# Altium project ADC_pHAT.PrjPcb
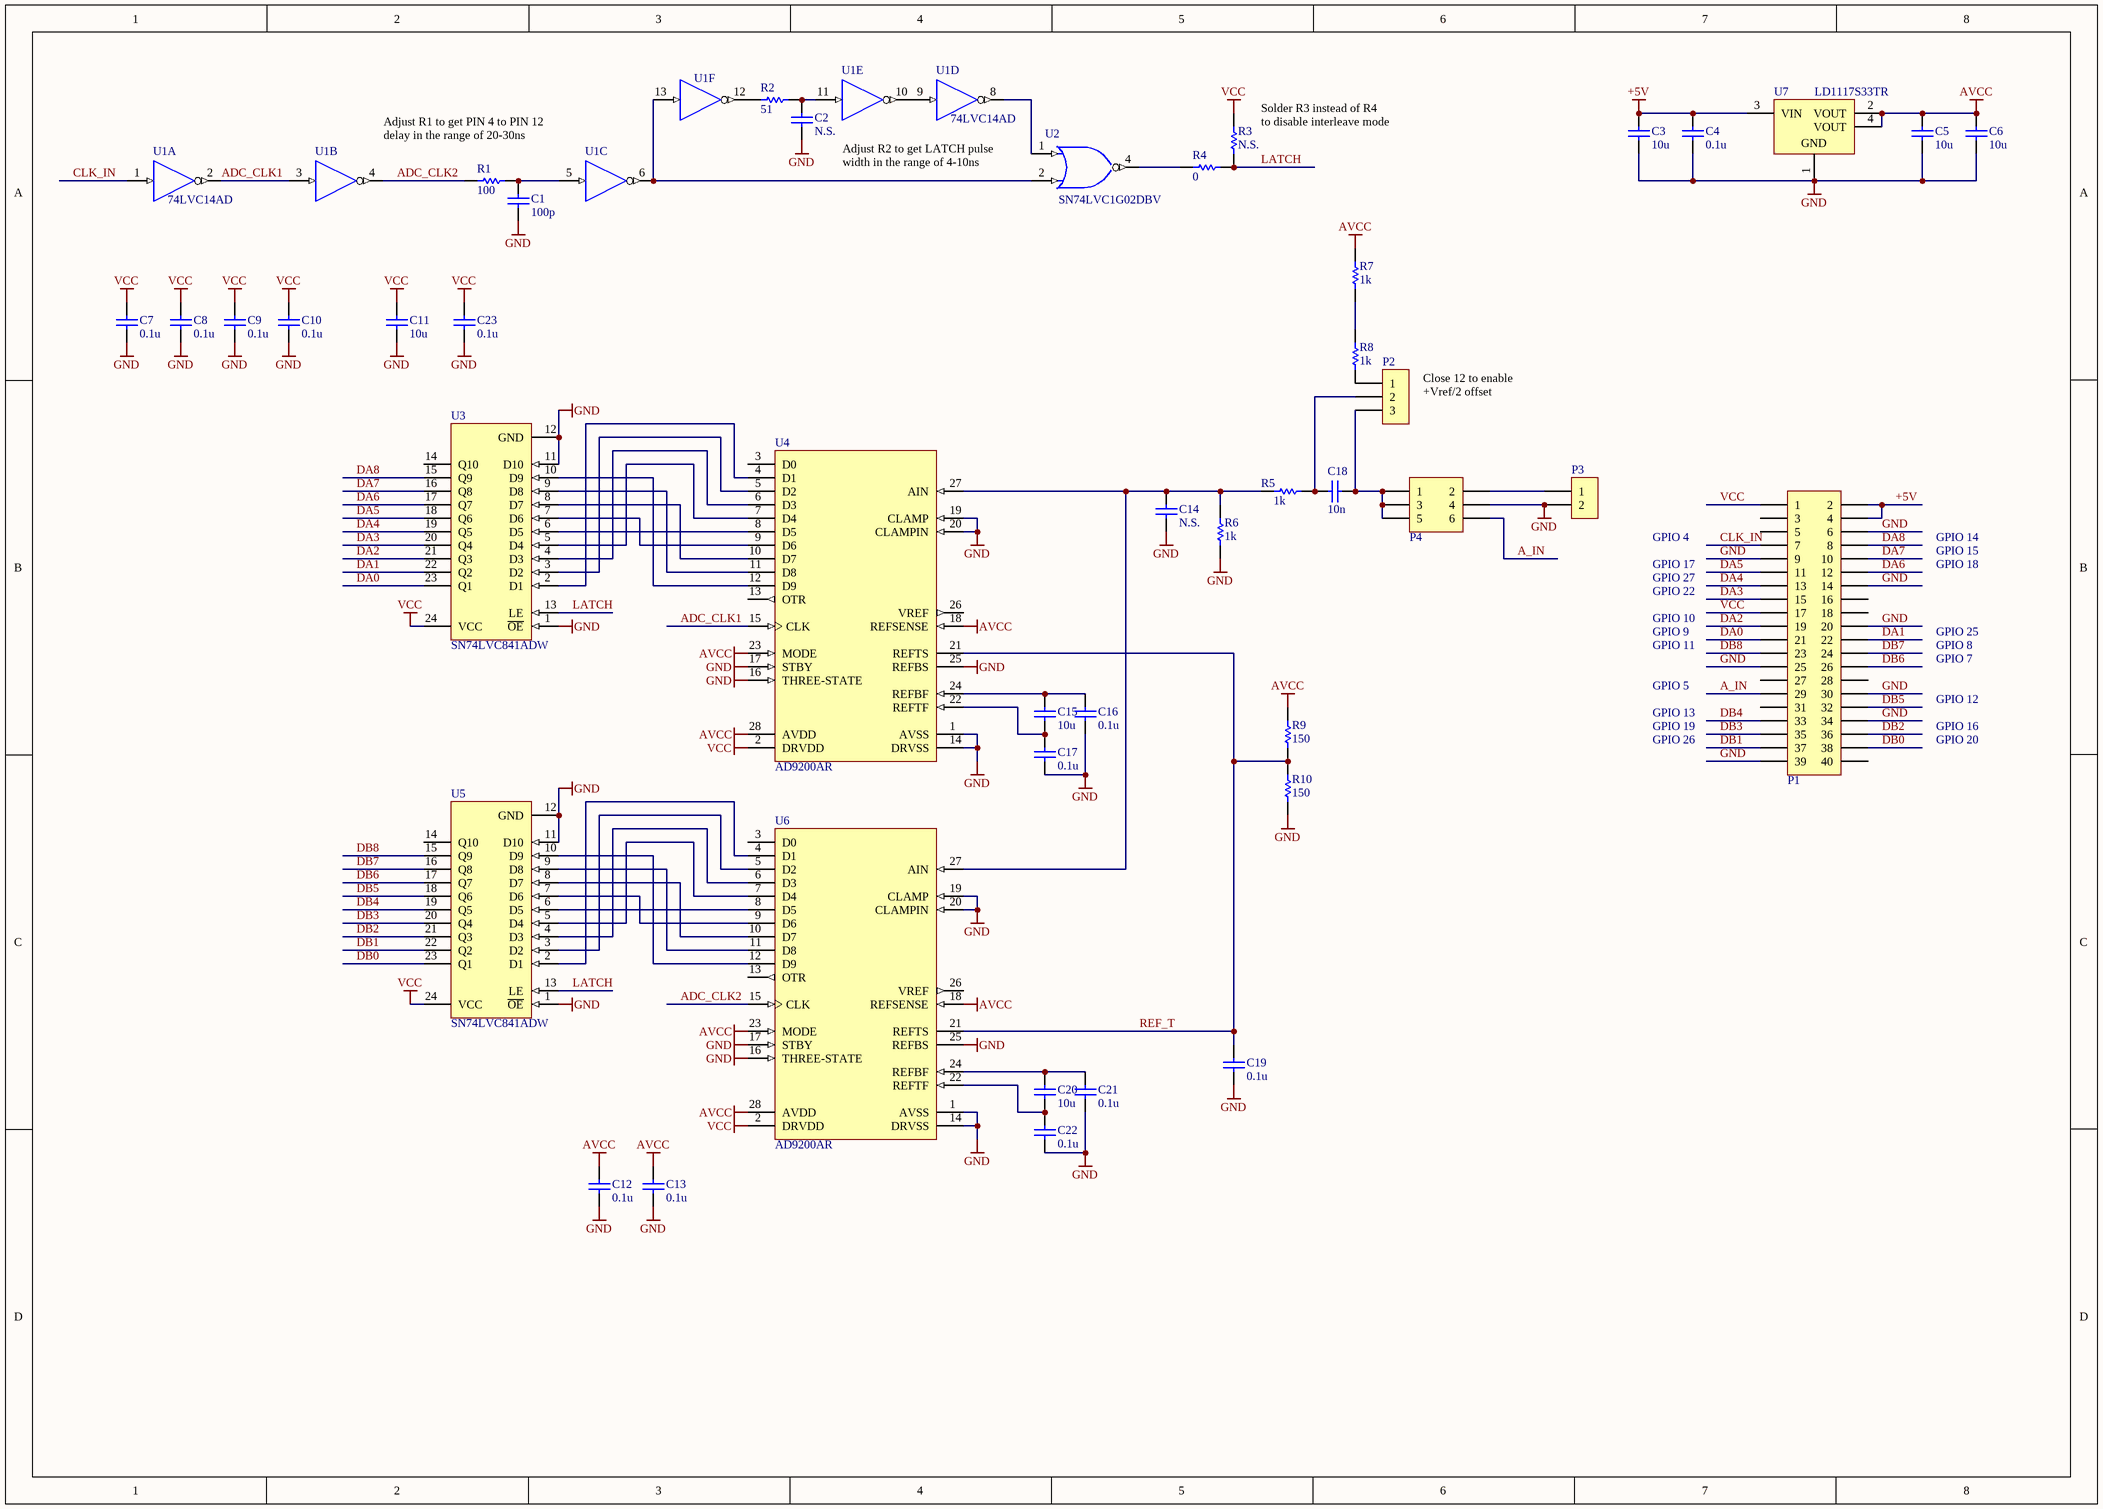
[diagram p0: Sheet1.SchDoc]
1 sheet, 44 parts. Net scope: global (net labels, ports and power ports of the same name join across sheets).
Board file: PCB1.PcbDoc

## Sheet Sheet1.SchDoc
size A3

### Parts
C1  100p  [0805RC]
C2  N.S.  [0805RC]
C3  10u  [1206RC]
C4  0.1u  [0805RC]
C5  10u  [1206RC]
C6  10u  [1206RC]
C7  0.1u  [0805RC]
C8  0.1u  [0805RC]
C9  0.1u  [0805RC]
C10  0.1u  [0805RC]
C11  10u  [1206RC]
C12  0.1u  [0805RC]
C13  0.1u  [0805RC]
C14  N.S.  [0805RC]
C15  10u  [1206RC]
C16  0.1u  [0805RC]
C17  0.1u  [0805RC]
C18  10n  [0805RC]
C19  0.1u  [0805RC]
C20  10u  [1206RC]
C21  0.1u  [0805RC]
C22  0.1u  [0805RC]
C23  0.1u  [0805RC]
P1  Header 20X2  [PLD-40]  (value not drawn)
P2  PLS-3  [PLS-3]  (value not drawn)
P3  Header 2  [SCSL-2]  (value not drawn)
P4  Header 3X2  [PBD-6]  (value not drawn)
R1  100  [0805R]
R2  51  [0805R]
R3  N.S.  [0805R]
R4  0  [0805R]
R5  1k  [0805R]
R6  1k  [0805R]
R7  1k  [0805R]
R8  1k  [0805R]
R9  150  [0805R]
R10  150  [0805R]
U1  74LVC14AD  [M14A_N]  (parts A,B,C,D,E,F of 6)
U2  SN74LVC1G02DBV  [SOT-23-5L]
U3  SN74LVC841ADW  [DW024_N]
U4  AD9200AR  [RS-28_N]
U5  SN74LVC841ADW  [DW024_N]
U6  AD9200AR  [RS-28_N]
U7  LD1117S33TR  [SOT223-4N]

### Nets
+5V: C3.2 C4.2 P1.2 P1.4 U7.3(VIN)
AVCC: C5.2 C6.2 C12.2 C13.2 R7.2 R9.2 U4.18(REFSENSE) U4.23(MODE) U4.28(AVDD) U6.18(REFSENSE) U6.23(MODE) U6.28(AVDD) U7.2(VOUT) U7.4(VOUT)
GND: C1.1 C2.1 C3.1 C4.1 C5.1 C6.1 C7.1 C8.1 C9.1 C10.1 C11.1 C12.1 C13.1 C14.1 C16.2 C17.1 C19.1 C21.2 C22.1 C23.1 P1.6 P1.9 P1.14 P1.20 P1.25 P1.30 P1.34 P1.39 P3.2 P4.4 R6.1 R10.1 U1.7(GND) U2.3(GND) U3.1(~{OE}) U3.11(D10) U3.12(GND) U4.1(AVSS) U4.14(DRVSS) U4.16(THREE-STATE) U4.17(STBY) U4.19(CLAMP) U4.20(CLAMPIN) U4.25(REFBS) U5.1(~{OE}) U5.11(D10) U5.12(GND) U6.1(AVSS) U6.14(DRVSS) U6.16(THREE-STATE) U6.17(STBY) U6.19(CLAMP) U6.20(CLAMPIN) U6.25(REFBS) U7.1(GND)
VCC: C7.2 C8.2 C9.2 C10.2 C11.2 C23.2 P1.1 P1.17 R3.2 U1.14(VCC) U2.5(VCC) U3.24(VCC) U4.2(DRVDD) U5.24(VCC) U6.2(DRVDD)
A_IN: P1.29 P4.6
ADC_CLK1: U1.2(~{O}) U1.3(I) U4.15(CLK)
ADC_CLK2: R1.1 U1.4(~{O}) U6.15(CLK)
CLK_IN: P1.7 U1.1(I)
DA0: P1.21 U3.23(Q1)
DA1: P1.22 U3.22(Q2)
DA2: P1.19 U3.21(Q3)
DA3: P1.15 U3.20(Q4)
DA4: P1.13 U3.19(Q5)
DA5: P1.11 U3.18(Q6)
DA6: P1.12 U3.17(Q7)
DA7: P1.10 U3.16(Q8)
DA8: P1.8 U3.15(Q9)
DB0: P1.38 U5.23(Q1)
DB1: P1.37 U5.22(Q2)
DB2: P1.36 U5.21(Q3)
DB3: P1.35 U5.20(Q4)
DB4: P1.33 U5.19(Q5)
DB5: P1.32 U5.18(Q6)
DB6: P1.26 U5.17(Q7)
DB7: P1.24 U5.16(Q8)
DB8: P1.23 U5.15(Q9)
LATCH: R3.1 R4.2 U3.13(LE) U5.13(LE)
REF_T: C19.2 R9.1 R10.2 U4.21(REFTS) U6.21(REFTS)
NetC1_2: C1.2 R1.2 U1.5(I)
NetC2_2: C2.2 R2.2 U1.11(I)
NetC14_2: C14.2 R5.1 R6.2 U4.27(AIN) U6.27(AIN)
NetC15_1: C15.1 C17.2 U4.22(REFTF)
NetC15_2: C15.2 C16.1 U4.24(REFBF)
NetC18_1: C18.1 P2.3 P4.1 P4.3 P4.5
NetC18_2: C18.2 P2.2 R5.2
NetC20_1: C20.1 C22.2 U6.22(REFTF)
NetC20_2: C20.2 C21.1 U6.24(REFBF)
NetP2_1: P2.1 R8.2
NetP3_1: P3.1 P4.2
NetR2_1: R2.1 U1.12(~{O})
NetR4_1: R4.1 U2.4(Y)
NetR7_1: R7.1 R8.1
NetU1_6: U1.6(~{O}) U1.13(I) U2.2(B)
NetU1_8: U1.8(~{O}) U2.1(A)
NetU1_9: U1.9(I) U1.10(~{O})
NetU3_2: U3.2(D1) U4.4(D1)
NetU3_3: U3.3(D2) U4.5(D2)
NetU3_4: U3.4(D3) U4.6(D3)
NetU3_5: U3.5(D4) U4.7(D4)
NetU3_6: U3.6(D5) U4.8(D5)
NetU3_7: U3.7(D6) U4.9(D6)
NetU3_8: U3.8(D7) U4.10(D7)
NetU3_9: U3.9(D8) U4.11(D8)
NetU3_10: U3.10(D9) U4.12(D9)
NetU5_2: U5.2(D1) U6.4(D1)
NetU5_3: U5.3(D2) U6.5(D2)
NetU5_4: U5.4(D3) U6.6(D3)
NetU5_5: U5.5(D4) U6.7(D4)
NetU5_6: U5.6(D5) U6.8(D5)
NetU5_7: U5.7(D6) U6.9(D6)
NetU5_8: U5.8(D7) U6.10(D7)
NetU5_9: U5.9(D8) U6.11(D8)
NetU5_10: U5.10(D9) U6.12(D9)

Not connected (* = marked no-connect by the designer): P1 3 5 16 18 27 28 31 40; U3 14(Q10); U4 3(D0) 13(OTR) 26(VREF); U5 14(Q10); U6 3(D0) 13(OTR) 26(VREF)

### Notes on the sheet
- Adjust R1 to get PIN 4 to PIN 12
  delay in the range of 20-30ns
- (near U1) Adjust R2 to get LATCH pulse
  width in the range of 4-10ns
- (near R3) Solder R3 instead of R4
  to disable interleave mode
- (near P2) Close 12 to enable
  +Vref/2 offset
- GPIO 17
- GPIO 27
- GPIO 4
- GPIO 18
- GPIO 15
- GPIO 14
- GPIO 22
- GPIO 10
- GPIO 9
- GPIO 11
- GPIO 8
- GPIO 25
- GPIO 5
- GPIO 13
- GPIO 12
- GPIO 7
- GPIO 19
- GPIO 26
- GPIO 20
- GPIO 16

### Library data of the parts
C1-C23 = Cap: Capacitor
P1 = Header 20X2: Header, 40-Pin
P2 = Header 3: 3-pin general header
P3 = Header 2: 2-pin general header
P4 = Header 3X2: Header, 3-Pin, Dual row
R1-R10 = Res1: Resistor
U1 = 74ACT14SC: Hex Schmitt-Trigger Inverter, 14-Pin SOIC, Commercial Grade; IC_Technology: ACT
U3 U5 = SN74LVC841ADW: 10-Bit Bus-Interface D-Type Latch with 3-State Outputs
U4 U6 = AD9200AR: Single 10-bit ADC Parallel 20MSPS; Part Number: AD9200; Manufacturer: Analog Devices; Resolution (Bits): 10; Channels: 1; Throughput Rate (SPS): 20M; Interface: Par; Packing: Tube
U7 = LD1117S33TR: Fixed Low Drop Positive Voltage Regulator, 3.3V, 4-Pin SOT-223, Tape and Reel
